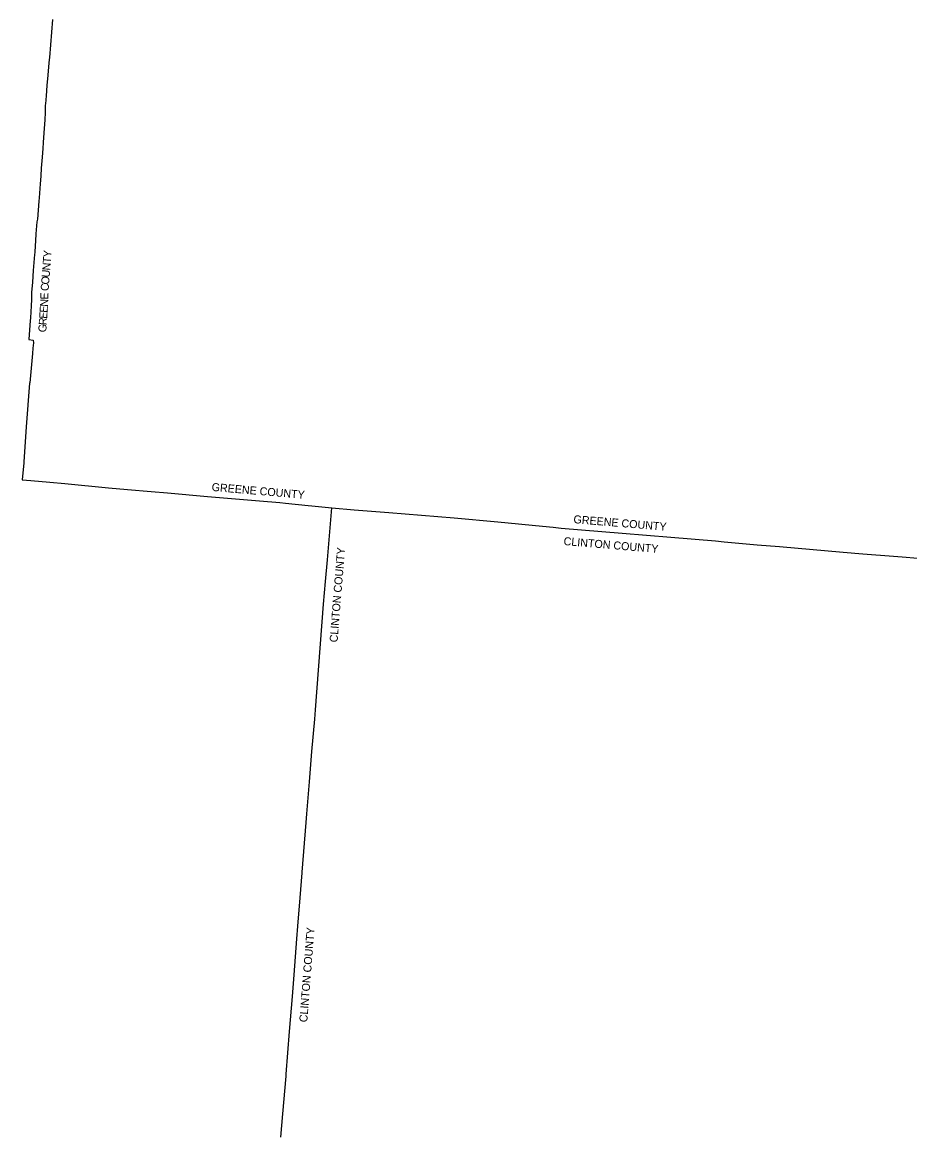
# Model space of a CAD drawing. Extents: x -51392 to 1635000, y 156707 to 696232.
# Drawn here: x -51392 to 59580, y 420919 to 560042 of the extents above; entities that cross this region are included whole.
import ezdxf

# ---------------------------------------------------------------- set-up
doc = ezdxf.new("R2010")
doc.units = 0
doc.layers.add('GM_X_Adjacent_County', color=7, linetype='Continuous')
doc.layers.add('GM_X_Adjacent_County_Text', color=7, linetype='Continuous')

msp = doc.modelspace()

# ---------------------------------------------------------------- linework, layer by layer
at = {"layer": 'GM_X_Adjacent_County'}
for points in [[(-47596, 560400), (-48001, 555638), (-48027, 555330), (-48056, 554987), (-48188, 553444), (-48299, 552136), (-48407, 550867), (-48494, 549846), (-48509, 549669), (-48516, 549561), (-48530, 549346), (-48543, 549167), (-48540, 548999), (-48533, 548881), (-48522, 548777), (-48563, 547858), (-48603, 547318), (-48687, 546222), (-48776, 545034), (-48834, 544270), (-48911, 543171), (-49012, 541801), (-49083, 540837), (-49084, 540823), (-49156, 539850), (-49283, 538121), (-49314, 537702), (-49480, 535445), (-49557, 535111), (-49677, 533597), (-49742, 532738), (-49772, 532129), (-49789, 531812), (-49804, 531626), (-49810, 531566), (-49834, 531274), (-49857, 531007), (-49898, 530521), (-50013, 529041), (-50126, 527565), (-50226, 526268), (-50240, 525829), (-50240, 525398), (-50277, 524626), (-50376, 523116), (-50401, 522745), (-50514, 521014), (-50555, 520389), (-50028, 520332), (-49988, 519972), (-50049, 519318), (-50112, 518659), (-50463, 514983), (-50468, 514929), (-50891, 509479), (-51193, 505123), (-51199, 504990), (-51392, 502854), (-50336, 502768), (-47953, 502573), (-46072, 502396), (-40588, 501861), (-38214, 501662), (-35265, 501415), (-33213, 501243), (-28240, 500793), (-21724, 500250), (-19200, 500041), (-18474, 499965), (-15628, 499667), (-15181, 499620), (-12692, 499359), (-9871, 499141), (-5556, 498806), (2621, 498139), (8074, 497613), (13664, 497074), (14990, 496946), (16010, 496847), (23627, 496211), (26670, 495956), (29723, 495701), (35280, 495237), (36388, 495137), (40489, 494769), (43302, 494561), (51263, 493831), (53719, 493635), (57563, 493320), (58642, 493232), (60591, 493072)], [(-19055, 420739), (-18807, 423647), (-18406, 428365), (-18385, 428619), (-17959, 433931), (-17612, 438318), (-17398, 441018), (-17041, 445523), (-16917, 447094), (-16637, 450644), (-16391, 453767), (-16385, 453841), (-15893, 460065), (-15809, 461126), (-15482, 465144), (-15175, 468923), (-14827, 472947), (-14725, 474122), (-13714, 487355), (-13473, 490185), (-13243, 492880), (-12692, 499359), (-9871, 499141), (-5556, 498806), (2621, 498139), (8074, 497613), (13664, 497074), (14990, 496946), (16010, 496847), (23627, 496211), (26670, 495956), (29723, 495701), (35280, 495237), (36388, 495137), (40489, 494769), (43302, 494561), (51263, 493831), (53719, 493635), (57563, 493320), (58642, 493232), (60591, 493072)]]:
    msp.add_lwpolyline(points, dxfattribs=at)

# ---------------------------------------------------------------- texts
at = {"layer": 'GM_X_Adjacent_County_Text'}
for s, rotation, p in [('Y', 85.48708, (-47780, 530633)), ('T', 85.48706, (-47838, 529888)), ('U', 85.50601, (-47977, 528124)), ('N', 85.48768, (-47908, 529006)), ('C', 85.91883, (-48103, 526432)), ('O', 85.60062, (-48045, 527243)), ('E', 88.41653, (-48143, 525393)), ('E', 86.45977, (-48236, 523726)), ('N', 87.04959, (-48189, 524484)), ('E', 86.27202, (-48285, 522976)), ('G', 86.20259, (-48397, 521280)), ('R', 86.2151, (-48339, 522163)), ('GREENE COUNTY', 355.08944, (-27739, 501494)), ('GREENE COUNTY', 355.25472, (17503, 497466)), ('CLINTON COUNTY', 355.21264, (16271, 494729)), ('CLINTON COUNTY', 85.35067, (-11979, 482531)), ('CLINTON COUNTY', 85.49678, (-15762, 435067))]:
    msp.add_text(s, height=1000, rotation=rotation, dxfattribs=at).set_placement(p)

doc.saveas('drawing.dxf')
